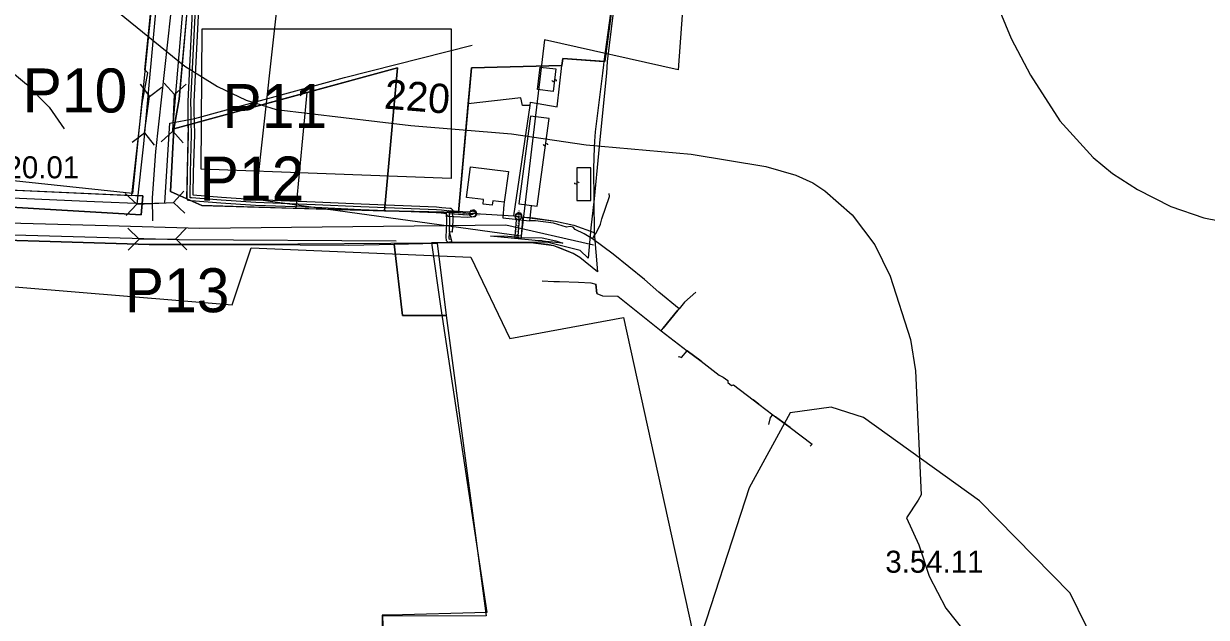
# Model space of a CAD drawing. Extents: x -662500 to -653478, y -1056827 to -1049993.
# Drawn here: x -660199.8 to -659796.6, y -1053979.7 to -1053777.2 of the extents above; entities that cross this region are included whole.
import ezdxf

# ---------------------------------------------------------------- set-up
doc = ezdxf.new("R2010")
doc.units = 0
for name, color, linetype in [('58', 7, 'Continuous'), ('Implicitní', 7, 'Continuous'), ('Vrstva 1', 7, 'Continuous'), ('Vrstva 11', 7, 'Continuous'), ('Vrstva 17', 7, 'Continuous'), ('Vrstva 24', 7, 'Continuous'), ('Vrstva 32', 7, 'Continuous'), ('Vrstva 37', 7, 'Continuous'), ('Vrstva 42', 7, 'Continuous'), ('Vrstva 45', 7, 'Continuous'), ('Vrstva 47', 7, 'Continuous'), ('Vrstva 48', 7, 'Continuous'), ('Vrstva 5', 7, 'Continuous'), ('Vrstva 61', 7, 'Continuous'), ('Vrstva 7', 7, 'Continuous')]:
    doc.layers.add(name, color=color, linetype=linetype)

# ---------------------------------------------------------------- blocks, each defined once
blk = doc.blocks.new('PSZ017')
at = {"layer": 'Vrstva 17'}
for points in [[(-10, 3.75), (-6.25, 0), (-10, -3.75)], [(-6.25, 0), (6.25, 0)], [(10, 3.75), (6.25, 0), (10, -3.75)]]:
    blk.add_lwpolyline(points, dxfattribs=at)
blk = doc.blocks.new('POINT_DISPLAY')
at = {"layer": 'Implicitní'}
blk.add_line((0, 0), (0, 0), dxfattribs=at)
blk = doc.blocks.new('$364')
at = {"layer": 'Implicitní'}
blk.add_lwpolyline([(-0.5, -7.5), (2.5, -6.5), (3.7, -3.4), (2.3, -0.7), (-2.5, 1), (-3.7, 3.8), (-2.3, 6.7), (0.5, 7.5)], dxfattribs=at)

msp = doc.modelspace()

# ---------------------------------------------------------------- linework, layer by layer
at = {"layer": '58'}
msp.add_lwpolyline([(-659953.41, -1053526.41), (-659966.09, -1053589.8), (-659979.45, -1053646.11), (-659986.05, -1053669.16), (-659992.56, -1053722.27), (-660000.86, -1053790.13), (-660001.11, -1053794.15), (-660003.29, -1053815.65), (-660003.85, -1053821.48), (-660005.39, -1053836.92), (-660006.52, -1053846.84), (-660007.35, -1053857.17), (-660010.12, -1053854.58), (-660021.49, -1053851.7), (-660054.09, -1053851.84), (-660060.83, -1053852), (-660057.69, -1053873.59), (-660041.94, -1053978.1), (-660074.73, -1053978.95), (-660077.64, -1053979.02), (-660077.87, -1053999.08)], dxfattribs=at)
at = {"layer": 'Vrstva 1'}
for p, q in [((-660106.89, -1053840.23), (-660103.21, -1053800.71)), ((-660144.25, -1053836.96), (-660143.69, -1053811.76))]:
    msp.add_line(p, q, dxfattribs=at)
for points in [[(-659985.28, -1053668.78), (-660002.01, -1053790.13), (-660002.16, -1053791.32), (-660002.5, -1053794.1), (-660004.94, -1053814.14), (-660005.18, -1053817.33), (-660005.34, -1053819.44), (-660005.58, -1053826.65), (-660005.29, -1053848.46), (-660004.16, -1053861.83), (-660010.2, -1053857.03), (-660012.44, -1053855.66), (-660017.12, -1053853.66), (-660019.03, -1053852.98), (-660021.16, -1053852.5), (-660026.92, -1053851.95), (-660035.99, -1053851.88), (-660050.1, -1053852.01), (-660052.3, -1053852.03), (-660058.85, -1053852.09), (-660055.8, -1053876.8), (-660042.1, -1053979.18), (-660077.54, -1053979.35), (-660076.72, -1054000.14)], [(-660051.64, -1053841.59), (-660048.25, -1053804.57), (-660047.13, -1053792.26), (-660016.34, -1053791.52), (-660016.06, -1053789.15), (-660002.01, -1053790.13)], [(-660032.72, -1053842.78), (-660027.21, -1053805.13), (-660027.04, -1053803.99), (-660017.98, -1053805.64), (-660016.34, -1053791.52)], [(-660027.21, -1053805.13), (-660029.72, -1053805.1), (-660030.32, -1053802.52), (-660048.25, -1053804.57)], [(-660051.64, -1053841.59), (-660032.72, -1053842.78), (-660031.72, -1053842.95), (-660026.12, -1053843.5), (-660018.51, -1053844.59), (-660012.27, -1053845.97), (-660005.29, -1053848.46)], [(-660055.8, -1053876.8), (-660070.7, -1053876.72), (-660073.51, -1053852.41), (-660058.85, -1053852.09)]]:
    msp.add_lwpolyline(points, dxfattribs=at)
for points in [[(-660148.64, -1053813.09), (-660143.69, -1053811.76), (-660103.21, -1053800.71), (-660072.33, -1053792.31), (-660076.83, -1053841.01), (-660106.89, -1053840.23), (-660139.06, -1053839.19), (-660144.25, -1053836.96), (-660149.76, -1053834.51)], [(-660023.73, -1053792.04), (-660018.42, -1053792.64), (-660019.34, -1053800.39), (-660024.7, -1053799.73)], [(-660027, -1053808.74), (-660031.07, -1053838.68), (-660024.79, -1053839.44), (-660020.73, -1053809.6)], [(-660047.53, -1053826.01), (-660034.52, -1053827.69), (-660035.98, -1053838.12), (-660039.93, -1053837.64), (-660040.15, -1053839.14), (-660043.23, -1053838.74), (-660043.04, -1053837.23), (-660048.89, -1053836.48)], [(-660011.23, -1053826.37), (-660011.22, -1053837.53), (-660006.47, -1053837.52), (-660006.5, -1053826.37)]]:
    msp.add_lwpolyline(points, close=True, dxfattribs=at)
at = {"layer": 'Vrstva 11'}
for points in [[(-660128.59, -1053535.41), (-660141.02, -1053666.13), (-660149.73, -1053774.2), (-660154.88, -1053820.83), (-660155.97, -1053836.63), (-660155.9, -1053844.5)], [(-660411.52, -1053823.45), (-660373.44, -1053828.35), (-660238.99, -1053844.22), (-660171.25, -1053846.11), (-660139.82, -1053846.95), (-660035.43, -1053845.88), (-660005.55, -1053852.66)]]:
    msp.add_lwpolyline(points, dxfattribs=at)
at = {"layer": 'Vrstva 17'}
for points in [[(-660093.08, -1053291.6), (-660096.38, -1053299.54), (-660103.97, -1053335.5), (-660111.56, -1053371.46), (-660148.84, -1053810.53)], [(-660409.95, -1053827.36), (-660292, -1053842.62), (-660239.28, -1053848.23), (-660146.85, -1053850.88), (-660072.84, -1053851.25)]]:
    msp.add_lwpolyline(points, dxfattribs=at)
at = {"layer": 'Vrstva 24'}
msp.add_lwpolyline([(-659830.33, -1054000), (-659832, -1053994), (-659843, -1053971.5), (-659874, -1053940), (-659913.5, -1053911.5), (-659924.5, -1053908), (-659938.5, -1053910), (-659952.5, -1053935.5), (-659971.5, -1053994), (-659976.58, -1054000)], dxfattribs=at)
at = {"layer": 'Vrstva 32'}
msp.add_lwpolyline([(-660407.56, -1053817.63), (-660406.83, -1053817.81), (-660364.13, -1053822.72), (-660321.75, -1053826.98), (-660286.16, -1053830.17), (-660234.71, -1053835.24), (-660175.64, -1053837.86), (-660158.79, -1053838.51), (-660151.75, -1053838.35), (-660149.96, -1053811.19), (-660141.45, -1053809.55), (-660090.4, -1053795.64), (-660046.88, -1053784.52)], dxfattribs=at)
at = {"layer": 'Vrstva 37'}
for points in [[(-660303.5, -1053230.44), (-660268.36, -1053230.44), (-660272.06, -1053456.27), (-660238.23, -1053464.08), (-660230.1, -1053441.95), (-660156.9, -1053423.64), (-660133.56, -1053315.41), (-660112.26, -1053315.31), (-660122.32, -1053372.39), (-660125.43, -1053404.18), (-660127.57, -1053442.13), (-660131.64, -1053497.5), (-660136.95, -1053566.03), (-660150.34, -1053712.33), (-660162.69, -1053835.19), (-660383.93, -1053811.56), (-660351.89, -1053606.5)], [(-660096.66, -1053668.18), (-659966.86, -1053657.36), (-659976.74, -1053792.99), (-660022.22, -1053782.75), (-660030.23, -1053849.74), (-660120.67, -1053837.24), (-660108.76, -1053729.2)], [(-660389.4, -1053839.98), (-660253.75, -1053862.77), (-660128.74, -1053873.18), (-660122.24, -1053853.65), (-660047.41, -1053856.91), (-660034.08, -1053884.58), (-659995.36, -1053877.42), (-659962.61, -1054026.33), (-660034.34, -1054033.17), (-660165.85, -1054002.41), (-660409.51, -1053977.34)]]:
    msp.add_lwpolyline(points, close=True, dxfattribs=at)
at = {"layer": 'Vrstva 42'}
for p, q in [((-660054.56, -1053844.32), (-660054.65, -1053842.02)), ((-660054.69, -1053848.29), (-660054.56, -1053844.32)), ((-660031.15, -1053843.07), (-660031.11, -1053842.73)), ((-660054.75, -1053850.28), (-660054.7, -1053848.69))]:
    msp.add_line(p, q, dxfattribs=at)
for points in [[(-660142.78, -1053807.34), (-660142.8, -1053803.76), (-660140.36, -1053754.17), (-660137.85, -1053724), (-660136.78, -1053713.11), (-660133.93, -1053679.11), (-660128.02, -1053621.83), (-660127.49, -1053612.47), (-660120.96, -1053547.99), (-660119.87, -1053525.87), (-660118.25, -1053505.95), (-660116.02, -1053485.23), (-660115.83, -1053483.2)], [(-660142.66, -1053836.62), (-660143.12, -1053836.59), (-660143.01, -1053828), (-660142.63, -1053815.06), (-660142.76, -1053810.73), (-660142.78, -1053807.34)], [(-660054.65, -1053842.02), (-660054.64, -1053841.13), (-660057.34, -1053840.88), (-660059.11, -1053840.7), (-660084.83, -1053839.68), (-660100.44, -1053838.97), (-660120.72, -1053838.23), (-660132.51, -1053837.4), (-660142.66, -1053836.62)], [(-660054.65, -1053842.02), (-660053.07, -1053842.11), (-660048.58, -1053842.38), (-660046.77, -1053842.15)], [(-660046.77, -1053842.15), (-660046.56, -1053842.12), (-660046.6, -1053841.74)], [(-660031.29, -1053850.59), (-660031.22, -1053849.67), (-660030.82, -1053844.06)], [(-660030.82, -1053844.06), (-660031.15, -1053843.11), (-660031.15, -1053843.07)], [(-660054.11, -1053850.77), (-660054.7, -1053850.79), (-660054.75, -1053850.28)], [(-660022.27, -1053851.47), (-660023.14, -1053851.27), (-660024.42, -1053851.26)]]:
    msp.add_lwpolyline(points, dxfattribs=at)
for points in [[(-660055.62, -1053841.55), (-660055, -1053841), (-660054.59, -1053841.02), (-660053.01, -1053841.11), (-660048.61, -1053841.37), (-660046.9, -1053841.16), (-660046.49, -1053841.1), (-660045.83, -1053841.61), (-660045.78, -1053842.02), (-660045.72, -1053842.43), (-660046.23, -1053843.09), (-660046.64, -1053843.14), (-660048.55, -1053843.38), (-660053.13, -1053843.11), (-660054.7, -1053843.02), (-660055.12, -1053842.99), (-660055.67, -1053842.37), (-660055.64, -1053841.96)], [(-660047.76, -1053842.27), (-660047.82, -1053841.86), (-660047.62, -1053841.61), (-660047.64, -1053841.43), (-660047.12, -1053840.79), (-660046.71, -1053840.74), (-660046.3, -1053840.7), (-660045.65, -1053841.22), (-660045.61, -1053841.63), (-660045.57, -1053842.01), (-660045.52, -1053842.42), (-660046.03, -1053843.06), (-660046.43, -1053843.11), (-660046.64, -1053843.14), (-660047.05, -1053843.19), (-660047.71, -1053842.69)], [(-660030.28, -1053850.69), (-660032.29, -1053850.49), (-660032.22, -1053849.59), (-660031.83, -1053844.19), (-660032.16, -1053843.23), (-660032.14, -1053842.99), (-660032.1, -1053842.57), (-660031.47, -1053842.04), (-660031.06, -1053842.08), (-660030.64, -1053842.11), (-660030.11, -1053842.75), (-660030.13, -1053842.98), (-660029.81, -1053843.92), (-660030.23, -1053849.74), (-660030.29, -1053850.63)], [(-660031.66, -1053844.03), (-660032.18, -1053843.38), (-660032.14, -1053842.97), (-660032.1, -1053842.63), (-660032.06, -1053842.22), (-660031.42, -1053841.7), (-660031.01, -1053841.74), (-660030.6, -1053841.78), (-660030.07, -1053842.42), (-660030.11, -1053842.83), (-660030.15, -1053843.18), (-660030.19, -1053843.59), (-660030.83, -1053844.11), (-660031.25, -1053844.07)], [(-660016, -1053852.09), (-660040.68, -1053849.67), (-660036.1, -1053849.6), (-660032.16, -1053849.92), (-660031.07, -1053850.19), (-660023.02, -1053850.28), (-660018.35, -1053851.34)], [(-660016, -1053852.09), (-660040.68, -1053849.67), (-660036.1, -1053849.6), (-660032.16, -1053849.92), (-660031.07, -1053850.19), (-660023.02, -1053850.28), (-660018.35, -1053851.34)], [(-660016, -1053852.09), (-660040.68, -1053849.67), (-660036.1, -1053849.6), (-660032.16, -1053849.92), (-660031.07, -1053850.19), (-660023.02, -1053850.28), (-660018.35, -1053851.34)]]:
    msp.add_lwpolyline(points, close=True, dxfattribs=at)
at = {"layer": 'Vrstva 45'}
for p, q in [((-660019.23, -1053845.3), (-660025.28, -1053844.53)), ((-660019.23, -1053845.3), (-660025.28, -1053844.53)), ((-660004.37, -1053869.26), (-660004.73, -1053866.12)), ((-660004.37, -1053869.26), (-660004.73, -1053866.12)), ((-659983.31, -1053868.82), (-659988.2, -1053864.53)), ((-659983.31, -1053868.82), (-659988.2, -1053864.53)), ((-659976.77, -1053874.99), (-659981.78, -1053881.13)), ((-659976.77, -1053874.99), (-659981.78, -1053881.13)), ((-659982.51, -1053881.96), (-659973.58, -1053888.81)), ((-659982.51, -1053881.96), (-659973.58, -1053888.81)), ((-659968.87, -1053892.36), (-659973.58, -1053888.81)), ((-659968.87, -1053892.36), (-659973.58, -1053888.81)), ((-659949.17, -1053907.04), (-659951.18, -1053905.54)), ((-659949.17, -1053907.04), (-659951.18, -1053905.54)), ((-659938.55, -1053914.97), (-659943.54, -1053911.33)), ((-659938.55, -1053914.97), (-659943.54, -1053911.33)), ((-659931.7, -1053921.37), (-659931.02, -1053920.67)), ((-659931.7, -1053921.37), (-659931.02, -1053920.67))]:
    msp.add_line(p, q, dxfattribs=at)
for points in [[(-660035.98, -1053838.17), (-660036.09, -1053838.87), (-660036.5, -1053843.45), (-660033.25, -1053843.74), (-660027.34, -1053844.46)], [(-660035.98, -1053838.17), (-660036.09, -1053838.87), (-660036.5, -1053843.45), (-660033.25, -1053843.74), (-660027.34, -1053844.46)], [(-660005.9, -1053850.61), (-660005.22, -1053849.31), (-660004.7, -1053848.66), (-660003.21, -1053845.61), (-660002.71, -1053843.77), (-660000.16, -1053836.14), (-660000.23, -1053835.19)], [(-660005.9, -1053850.61), (-660005.22, -1053849.31), (-660004.7, -1053848.66), (-660003.21, -1053845.61), (-660002.71, -1053843.77), (-660000.16, -1053836.14), (-660000.23, -1053835.19)], [(-660026.8, -1053839.27), (-660027.24, -1053843.61), (-660027.34, -1053844.46)], [(-660026.8, -1053839.27), (-660027.24, -1053843.61), (-660027.34, -1053844.46)], [(-660005.9, -1053850.61), (-660008.78, -1053848.86), (-660011.84, -1053847.41), (-660012.55, -1053846.6), (-660013.55, -1053846.38), (-660014.74, -1053846.62), (-660019.23, -1053845.3), (-660025.28, -1053844.53), (-660027.34, -1053844.46)], [(-660005.9, -1053850.61), (-660008.78, -1053848.86), (-660011.84, -1053847.41), (-660012.55, -1053846.6), (-660013.55, -1053846.38), (-660014.74, -1053846.62), (-660019.23, -1053845.3), (-660025.28, -1053844.53), (-660027.34, -1053844.46)], [(-659976.34, -1053874.46), (-659983.31, -1053868.82), (-659988.2, -1053864.53), (-659998.87, -1053855.83), (-660005.9, -1053850.61)], [(-659976.34, -1053874.46), (-659983.31, -1053868.82), (-659988.2, -1053864.53), (-659998.87, -1053855.83), (-660005.9, -1053850.61)], [(-660023.06, -1053864.89), (-660019.07, -1053865.13), (-660017.17, -1053865.15), (-660010.67, -1053865.42), (-660006.5, -1053865.67), (-660004.73, -1053866.12), (-660004.37, -1053869.26), (-660002.45, -1053870.04), (-659997.27, -1053870.21), (-659982.51, -1053881.96)], [(-660023.06, -1053864.89), (-660019.07, -1053865.13), (-660017.17, -1053865.15), (-660010.67, -1053865.42), (-660006.5, -1053865.67), (-660004.73, -1053866.12), (-660004.37, -1053869.26), (-660002.45, -1053870.04), (-659997.27, -1053870.21), (-659982.51, -1053881.96)], [(-659970.71, -1053868.82), (-659974.56, -1053872.16), (-659976.34, -1053874.46)], [(-659970.71, -1053868.82), (-659974.56, -1053872.16), (-659976.34, -1053874.46)], [(-659982.51, -1053881.96), (-659981.78, -1053881.13), (-659976.77, -1053874.99), (-659976.34, -1053874.46)], [(-659982.51, -1053881.96), (-659981.78, -1053881.13), (-659976.77, -1053874.99), (-659976.34, -1053874.46)], [(-659976.54, -1053890.95), (-659976.39, -1053890.74), (-659975.53, -1053891.1), (-659973.58, -1053888.81)], [(-659976.54, -1053890.95), (-659976.39, -1053890.74), (-659975.53, -1053891.1), (-659973.58, -1053888.81)], [(-659973.58, -1053888.81), (-659968.87, -1053892.36), (-659962.67, -1053897.15), (-659961.37, -1053897.74), (-659959.77, -1053898.94), (-659959.82, -1053899.67), (-659958.47, -1053900.69), (-659957.84, -1053900.44), (-659951.18, -1053905.54), (-659949.17, -1053907.04), (-659944.43, -1053910.65)], [(-659973.58, -1053888.81), (-659968.87, -1053892.36), (-659962.67, -1053897.15), (-659961.37, -1053897.74), (-659959.77, -1053898.94), (-659959.82, -1053899.67), (-659958.47, -1053900.69), (-659957.84, -1053900.44), (-659951.18, -1053905.54), (-659949.17, -1053907.04), (-659944.43, -1053910.65)], [(-659945.76, -1053913.98), (-659945.19, -1053911.6), (-659944.43, -1053910.65)], [(-659945.76, -1053913.98), (-659945.19, -1053911.6), (-659944.43, -1053910.65)], [(-659944.43, -1053910.65), (-659943.54, -1053911.33), (-659938.55, -1053914.97), (-659931.02, -1053920.67)], [(-659944.43, -1053910.65), (-659943.54, -1053911.33), (-659938.55, -1053914.97), (-659931.02, -1053920.67)]]:
    msp.add_lwpolyline(points, dxfattribs=at)
at = {"layer": 'Vrstva 47'}
for points in [[(-660136.85, -1053724.09), (-660139.36, -1053754.23), (-660141.8, -1053803.78), (-660141.78, -1053807.33), (-660141.76, -1053810.72), (-660141.63, -1053815.06), (-660142.01, -1053828.02), (-660142.11, -1053835.66), (-660132.43, -1053836.41), (-660120.67, -1053837.24), (-660100.4, -1053837.97), (-660084.79, -1053838.68), (-660059.04, -1053839.7), (-660057.24, -1053839.89), (-660054.55, -1053840.13), (-660054.17, -1053840.17), (-660053.64, -1053840.74), (-660053.64, -1053841.13), (-660053.65, -1053842), (-660053.56, -1053844.32), (-660053.69, -1053848.39), (-660054.82, -1053848.28)], [(-660054.82, -1053848.28), (-660053.83, -1053851.76), (-660054.66, -1053851.79), (-660055.06, -1053851.81), (-660055.65, -1053851.29), (-660055.69, -1053850.9), (-660055.75, -1053850.32), (-660055.57, -1053844.33), (-660055.65, -1053842.04), (-660057.44, -1053841.88), (-660059.19, -1053841.69), (-660084.87, -1053840.68), (-660100.48, -1053839.97), (-660120.78, -1053839.23), (-660132.58, -1053838.4), (-660142.73, -1053837.62), (-660143.2, -1053837.59), (-660143.59, -1053837.56), (-660144.13, -1053836.97), (-660144.12, -1053836.58), (-660144.01, -1053827.98), (-660143.63, -1053815.06), (-660143.76, -1053810.75), (-660143.78, -1053807.34), (-660143.8, -1053803.74), (-660141.36, -1053754.1)]]:
    msp.add_lwpolyline(points, dxfattribs=at)
at = {"layer": 'Vrstva 48'}
msp.add_lwpolyline([(-660138.99, -1053778.97), (-660054.08, -1053778.97), (-660054.08, -1053830.07), (-660139.31, -1053826.81)], close=True, dxfattribs=at)
at = {"layer": 'Vrstva 5'}
for points in [[(-660118.91, -1053503.44), (-660126.59, -1053589.2), (-660138.85, -1053712.12), (-660146.82, -1053803.03), (-660148.64, -1053813.09), (-660149.76, -1053834.51), (-660139.06, -1053839.19), (-660076.83, -1053841.01), (-660051.64, -1053841.59), (-660032.72, -1053842.78), (-660018.51, -1053844.59), (-660012.27, -1053845.97), (-660005.29, -1053848.46), (-660004.16, -1053861.83), (-660010.2, -1053857.03), (-660012.44, -1053855.66), (-660019.03, -1053852.98), (-660026.92, -1053851.95), (-660058.85, -1053852.09), (-660122.2, -1053852.55), (-660157.09, -1053852.56), (-660239.81, -1053850.04)], [(-659953.22, -1053525.2), (-659985.7, -1053668.71), (-660001.66, -1053790.17), (-660016.06, -1053789.15), (-660016.34, -1053791.52), (-660047.13, -1053792.26), (-660051.64, -1053841.59), (-660076.83, -1053841.01), (-660072.33, -1053792.31), (-660148.64, -1053813.09), (-660146.82, -1053803.03), (-660144.24, -1053774.31), (-660138.85, -1053712.12), (-660126.59, -1053589.2), (-660118.91, -1053503.44)], [(-660659.38, -1053604.53), (-660591.82, -1053615.12), (-660481.41, -1053634.1), (-660378.28, -1053653.76), (-660398.86, -1053759.98), (-660407.77, -1053814.99), (-660406.28, -1053815.33), (-660305.92, -1053826.68), (-660234.87, -1053832.54), (-660162.97, -1053835.81), (-660159.44, -1053804.48), (-660157.5, -1053793.95), (-660158.49, -1053793), (-660150.34, -1053712.33), (-660136.95, -1053566.03)], [(-660235.12, -1053837.99), (-660159.73, -1053842.4), (-660159.25, -1053835.99), (-660162.97, -1053835.81), (-660159.44, -1053804.48), (-660157.5, -1053793.95), (-660158.49, -1053793), (-660150.34, -1053712.33), (-660136.95, -1053566.03)]]:
    msp.add_lwpolyline(points, dxfattribs=at)
for points in [[(-660407.77, -1053814.99), (-660406.28, -1053815.33), (-660305.92, -1053826.68), (-660234.87, -1053832.54), (-660159.25, -1053835.99), (-660159.73, -1053842.4), (-660235.12, -1053837.99), (-660406.12, -1053820.42), (-660408.56, -1053819.81)], [(-660410.34, -1053829.44), (-660358.01, -1053836.31), (-660307.68, -1053842.9), (-660239.81, -1053850.04), (-660157.09, -1053852.56), (-660122.2, -1053852.55), (-660088.98, -1053852.83), (-660073.51, -1053852.41), (-660070.7, -1053876.72), (-660055.8, -1053876.8), (-660042.1, -1053979.18), (-660077.54, -1053979.35), (-660076.72, -1054000.14), (-660201.14, -1054026.33), (-660241.12, -1054042.52), (-660324.21, -1054084.16), (-660365.41, -1054097.44), (-660421.6, -1054104.02), (-660440.68, -1054035.17), (-660444.92, -1054007.24), (-660438.94, -1053983.58)]]:
    msp.add_lwpolyline(points, close=True, dxfattribs=at)
at = {"layer": 'Vrstva 61'}
msp.add_lwpolyline([(-660103.33, -1053285.76), (-660108.12, -1053300.67), (-660119.61, -1053361.23), (-660123.15, -1053400.36), (-660134.78, -1053552.31), (-660158.95, -1053818.23), (-660161.28, -1053838.75)], dxfattribs=at)
at = {"layer": 'Vrstva 7'}
for p, q in [((-659874.38, -1053755.11), (-659863.19, -1053782.32)), ((-660179.92, -1053763.19), (-660144.92, -1053791.67)), ((-659863.19, -1053782.32), (-659856.53, -1053794.79)), ((-660206.43, -1053791.53), (-660198.91, -1053797.91)), ((-660144.92, -1053791.67), (-660133.72, -1053798.62)), ((-659856.53, -1053794.79), (-659846.61, -1053810.38)), ((-660198.91, -1053797.91), (-660191.12, -1053805.7)), ((-660133.72, -1053798.62), (-660123.95, -1053803.29)), ((-660191.12, -1053805.7), (-660186.02, -1053813.07)), ((-660123.95, -1053803.29), (-660113.74, -1053806.55)), ((-660113.74, -1053806.55), (-660067.83, -1053811.94)), ((-660067.83, -1053811.94), (-660033.53, -1053814.77)), ((-659846.61, -1053810.38), (-659835.27, -1053822.85)), ((-660033.53, -1053814.77), (-660008.02, -1053818.6)), ((-660008.02, -1053818.6), (-659972.31, -1053821.72)), ((-659972.31, -1053821.72), (-659946.8, -1053825.97)), ((-659946.8, -1053825.97), (-659936.6, -1053828.95)), ((-659835.27, -1053822.85), (-659828.61, -1053828.38)), ((-659936.6, -1053828.95), (-659930.79, -1053831.5)), ((-659828.61, -1053828.38), (-659820.11, -1053833.76)), ((-659930.79, -1053831.5), (-659926.68, -1053834.19)), ((-659820.11, -1053833.76), (-659808.77, -1053839.57)), ((-659926.68, -1053834.19), (-659917.32, -1053842.41)), ((-659808.77, -1053839.57), (-659797.43, -1053843.4)), ((-659917.32, -1053842.41), (-659909.67, -1053852.61)), ((-659797.43, -1053843.4), (-659783.83, -1053846.09)), ((-659909.67, -1053852.61), (-659904.43, -1053863.38)), ((-659904.43, -1053863.38), (-659897.48, -1053884.92)), ((-659897.48, -1053884.92), (-659895.78, -1053895.69)), ((-659895.78, -1053895.69), (-659893.84, -1053937.9)), ((-659893.84, -1053937.9), (-659894.92, -1053939.7)), ((-659894.92, -1053939.7), (-659898.87, -1053945.8)), ((-659898.87, -1053945.8), (-659894.65, -1053954.93)), ((-659894.65, -1053954.93), (-659891.11, -1053965.7)), ((-659891.11, -1053965.7), (-659885.44, -1053976.61)), ((-659885.44, -1053976.61), (-659873.53, -1053991.49))]:
    msp.add_line(p, q, dxfattribs=at)

# ---------------------------------------------------------------- block references
at = {"layer": 'Vrstva 1', "xscale": 0.1}
for p, yscale, rotation in [((-660018.9, -1053796.69), 0.09999999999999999, 83.22784899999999), ((-660021.93, -1053818.43), 0.10000000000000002, -97.74576200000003), ((-660011.23, -1053831.6), 0.10000000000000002, 90.051775)]:
    msp.add_blockref('$364', p, dxfattribs=dict(at, yscale=yscale, rotation=rotation))
at = {"layer": 'Vrstva 1', "xscale": 0.1, "yscale": 0.10000000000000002}
for p in [(-660027.04, -1053803.99), (-660043.04, -1053837.23), (-660031.07, -1053838.68)]:
    msp.add_blockref('POINT_DISPLAY', p, dxfattribs=at)
at = {"layer": 'Vrstva 17'}
for p, rotation in [((-660157.76, -1053808.26), 82.39672901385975), ((-660148.69, -1053807.67), 87.25759419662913), ((-660155.04, -1053838.51), 2.1570637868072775), ((-660154.26, -1053850.67), 0.5686235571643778)]:
    msp.add_blockref('PSZ017', p, dxfattribs=dict(at, rotation=rotation))

# ---------------------------------------------------------------- texts
for s, p in [('P10', (-660200.19, -1053807.51)), ('P11', (-660132.06, -1053812.81)), ('P12', (-660139.83, -1053837.54)), ('P13', (-660165.37, -1053875.65))]:
    msp.add_text(s, height=15, rotation=360, dxfattribs=at).set_placement(p)
at = {"layer": 'Vrstva 24'}
for s, p in [('3.20.01', (-660214.37, -1053829.97)), ('3.54.11', (-659906.07, -1053964.5))]:
    msp.add_text(s, height=7.5, dxfattribs=at).set_placement(p)
at = {"layer": 'Vrstva 42'}
for s, rotation, p in [('PE  32.00', 356.5623, (-660053.86, -1053842.07)), ('Ocel  25.00', 356.5623, (-660049.61, -1053842.32)), ('Ocel  25.00', 85.9437, (-660030.97, -1053846.17)), ('PE  32.00', 85.9437, (-660031.28, -1053850.43))]:
    msp.add_text(s, height=0.75, rotation=rotation, dxfattribs=at).set_placement(p)
at = {"layer": 'Vrstva 7'}
msp.add_text('220', height=10, rotation=355.2762, dxfattribs=at).set_placement((-660077.16, -1053806.15))

doc.saveas('drawing.dxf')
